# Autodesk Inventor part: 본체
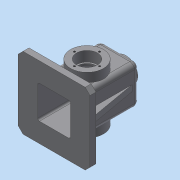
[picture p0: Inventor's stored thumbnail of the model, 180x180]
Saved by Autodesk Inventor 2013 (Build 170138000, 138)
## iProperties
Created: 2018-10
Part Number: 본체
Material: 일반
Document SubType Name: Modeling
Designer: Administrator
Density: 1 g/cm^3
Author: Administrator
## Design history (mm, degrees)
sketch "스케치1"
  geometry: L1 (-32.5, -32.5)-(32.5, -32.5); L2 (32.5, -32.5)-(32.5, 32.5); L3 (32.5, 32.5)-(-32.5, 32.5); L4 (-32.5, 32.5)-(-32.5, -32.5); L5 (-32.5, -32.5)-(32.5, 32.5); L6 (32.5, -32.5)-(-32.5, 32.5); 1 further point
  constraints: 12 end point, 2 midpoint, 2 parallel, 1 horizontal, 1 perpendicular
  dimensions: "d0" = 65 distance of L3.end L2.end; "d1" = 65 distance of L2.end L1.end
extrude "돌출1" new body sketch "스케치1" stored distance "d2" = 110; taper "d3" = 0 deg
fillet "모깎기1" dims "d4" = 8
feature "쉘1" dims "d5" = 5
node "작업 평면1"
sketch "스케치3"
  geometry: C1 r 27.5 at (24.5, 55); 1 further point
  constraints: 1 centre point, 1 coincident
  dimensions: "d10" = 55 diameter of C1
extrude "돌출3" join sketch "스케치3" stored distance "d11" = 15; taper "d12" = 0 deg
sketch "스케치4"
  geometry: C1 r 27.5 at (0, 0) reference; C2 r 17.5 at (0, 0)
  constraints: 1 centre point, 1 coincident
  dimensions: "d13" = 35 diameter of C2
extrude "돌출4" cut sketch "스케치4" distance "d14" = 17; taper "d15" = 0 deg
sketch "스케치5"
  geometry: C1 r 17.5 at (0, 0) reference; C2 r 15 at (0, 0)
  constraints: 1 centre point, 1 coincident
  dimensions: "d16" = 30 diameter of C2
extrude "돌출5" cut sketch "스케치5" distance "d17" = 3; taper "d18" = 0 deg
sketch "스케치6"
  geometry: C1 r 17.5 at (0, 0) reference; 1 further point
  constraints: 1 vertical alignment
  dimensions: "d19" = 21 distance of C1.centre point (0, 21)
hole "구멍1" sketch "스케치6" at (0, 21) diameter "d20" = 3.242; stored, may be unused: countersink angle "d24" = 90 deg, drill point angle "d26" = 118 deg; dims "d21" = 8, "d22" = 4, "d23" = 2, "d25" = 10
node "작업 평면2"
sketch "스케치7"
  geometry: C1 r 20 at (0, 0); 1 further point
  constraints: 1 centre point, 1 coincident
  dimensions: "d31" = 40 diameter of C1
extrude "돌출6" join sketch "스케치7" stored distance "d32" = 3; taper "d33" = 7 deg
hole "구멍2" diameter "d36" = 22.835; stored, may be unused: countersink angle "d40" = 90 deg, drill point angle "d42" = 0 deg; dims "d34" = 10, "d35" = 10, "d37" = 8, "d38" = 4, "d39" = 2, "d41" = 10
sketch "스케치8"
  geometry: L1 (-24.5, -32.5)-(24.5, -32.5) reference; L2 (32.5, -24.5)-(32.5, 24.5) reference; L3 (24.5, 32.5)-(-24.5, 32.5) reference; L4 (-32.5, 24.5)-(-32.5, -24.5) reference; L5 (-60, -60)-(60, -60); L6 (60, -60)-(60, 60); L7 (60, 60)-(-60, 60); L8 (-60, 60)-(-60, -60); L9 (-60, -60)-(60, 60); L10 (60, -60)-(-60, 60); A1 r 8 centre (24.5, -24.5) between (24.5, -32.5) and (32.5, -24.5) reference; A2 r 8 centre (24.5, 24.5) between (32.5, 24.5) and (24.5, 32.5) reference; A3 r 8 centre (-24.5, 24.5) between (-24.5, 32.5) and (-32.5, 24.5) reference; A4 r 8 centre (-24.5, -24.5) between (-32.5, -24.5) and (-24.5, -32.5) reference; 1 further point
  constraints: 12 end point, 2 midpoint, 2 parallel, 1 horizontal, 1 perpendicular
  dimensions: "d43" = 120 distance of L7.end L6.end; "d44" = 120 distance of L6.end L5.end
extrude "돌출7" join sketch "스케치8" distance "d45" = 10; taper "d46" = 0 deg
chamfer "모따기1" distance "d47" = 8; stored, may be unused: second distance "d48" = 2, angle "d49" = 45 deg
sketch "스케치9"
  geometry: L1 (20, 65)-(21.228, 55) reference; L2 (21.228, 55)-(24.5, 55) reference; L3 (32.5, 47)-(32.5, -45) reference; L4 (32.5, -45)-(60, -45) reference; L5 (60, -45)-(60, -55) reference; L6 (60, -55)-(27.5, -55) reference; L7 (27.5, -55)-(27.5, 47) reference; L8 (24.5, 50)-(11.418, 50) reference; L9 (11.418, 50)-(11.418, 65) reference; L10 (11.418, 65)-(20, 65) reference; L11 (-24.5, 55)-(-21.228, 55) reference; L12 (-21.228, 55)-(-20, 65) reference; L13 (-20, 65)-(-11.418, 65) reference; L14 (-11.418, 65)-(-11.418, 50) reference; L15 (-11.418, 50)-(-24.5, 50) reference; L16 (-27.5, 47)-(-27.5, -55) reference; L17 (-27.5, -55)-(-60, -55) reference; L18 (-60, -55)-(-60, -45) reference; L19 (-60, -45)-(-32.5, -45) reference; L20 (-32.5, -45)-(-32.5, 47) reference; L21 (-48, -45)-(-42.191, -12.053); A1 r 8 centre (24.5, 47) between (32.5, 47) and (24.5, 55) reference; A2 r 3 centre (24.5, 47) between (27.5, 47) and (24.5, 50) reference; A3 r 8 centre (-24.5, 47) between (-24.5, 55) and (-32.5, 47) reference; A4 r 3 centre (-24.5, 47) between (-24.5, 50) and (-27.5, 47) reference; 1 further point
  constraints: 2 end point, 1 point on line
  dimensions: "d50" = 10 deg angle of L21 L18; "d51" = 12 distance from line of L21.start L18
feature "리브1" sketch "스케치9" dims "d52" = 1, "d53" = 10, "d54" = 0, "d55" = 0, "d56" = 1, "d57" = 1
sketch "스케치10"
  geometry: L1 (-17.5, -30.5)-(-17.5, -47.5) reference; L2 (-17.5, -47.5)-(-19.379, -47.5) reference; L3 (-19.379, -47.5)-(-19.379, -37.5) reference; L4 (-19.379, -37.5)-(-21, -36.526) reference; L5 (-21, -36.526)-(-22.621, -37.5) reference; L6 (-22.621, -37.5)-(-22.621, -47.5) reference; L7 (-22.621, -47.5)-(-27.5, -47.5) reference; L8 (-27.5, -47.5)-(-27.5, -32.5) reference; L9 (-27.5, -32.5)-(-45, -32.5) reference; L10 (-45, -32.5)-(-45, -60) reference; L11 (-45, -60)-(-55, -60) reference; L12 (-55, -60)-(-55, -27.5) reference; L13 (-55, -27.5)-(-15, -27.5) reference; L14 (-15, -27.5)-(-15, -30.5) reference; L15 (-15, -30.5)-(-17.5, -30.5) reference; L16 (27.5, -32.5)-(27.5, -47.5) reference; L17 (27.5, -47.5)-(22.621, -47.5) reference; L18 (22.621, -47.5)-(22.621, -37.5) reference; L19 (22.621, -37.5)-(21, -36.526) reference; L20 (21, -36.526)-(19.379, -37.5) reference; L21 (19.379, -37.5)-(19.379, -47.5) reference; L22 (19.379, -47.5)-(17.5, -47.5) reference; L23 (17.5, -47.5)-(17.5, -30.5) reference; L24 (17.5, -30.5)-(15, -30.5) reference; L25 (15, -30.5)-(15, -27.5) reference; L26 (15, -27.5)-(47, -27.5) reference; L27 (50, -24.5)-(50, -11.418) reference; L28 (50, -11.418)-(65, -11.418) reference; L29 (65, -11.418)-(65, -20) reference; L30 (65, -20)-(55, -21.228) reference; L31 (55, -21.228)-(55, -24.5) reference; L32 (47, -32.5)-(27.5, -32.5) reference; L33 (27.5, 47.5)-(27.5, 32.5) reference; L34 (27.5, 32.5)-(47, 32.5) reference; L35 (55, 24.5)-(55, 21.228) reference; L36 (55, 21.228)-(65, 20) reference; L37 (65, 20)-(65, 11.418) reference; L38 (65, 11.418)-(50, 11.418) reference; L39 (50, 11.418)-(50, 24.5) reference; L40 (47, 27.5)-(15, 27.5) reference; L41 (15, 27.5)-(15, 30.5) reference; L42 (15, 30.5)-(17.5, 30.5) reference; L43 (17.5, 30.5)-(17.5, 47.5) reference; L44 (17.5, 47.5)-(19.379, 47.5) reference; L45 (19.379, 47.5)-(19.379, 37.5) reference; L46 (19.379, 37.5)-(21, 36.526) reference; L47 (21, 36.526)-(22.621, 37.5) reference; L48 (22.621, 37.5)-(22.621, 47.5) reference; L49 (22.621, 47.5)-(27.5, 47.5) reference; L50 (-27.5, 32.5)-(-27.5, 47.5) reference; L51 (-27.5, 47.5)-(-22.621, 47.5) reference; L52 (-22.621, 47.5)-(-22.621, 37.5) reference; L53 (-22.621, 37.5)-(-21, 36.526) reference; L54 (-21, 36.526)-(-19.379, 37.5) reference; L55 (-19.379, 37.5)-(-19.379, 47.5) reference; L56 (-19.379, 47.5)-(-17.5, 47.5) reference; L57 (-17.5, 47.5)-(-17.5, 30.5) reference; L58 (-17.5, 30.5)-(-15, 30.5) reference; L59 (-15, 30.5)-(-15, 27.5) reference; L60 (-15, 27.5)-(-55, 27.5) reference; L61 (-55, 27.5)-(-55, 60) reference; L62 (-55, 60)-(-45, 60) reference; L63 (-45, 60)-(-45, 32.5) reference; L64 (-45, 32.5)-(-27.5, 32.5) reference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; A1 r 3 centre (47, -24.5) between (47, -27.5) and (50, -24.5) reference; A2 r 8 centre (47, -24.5) between (47, -32.5) and (55, -24.5) reference; A3 r 8 centre (47, 24.5) between (55, 24.5) and (47, 32.5) reference; A4 r 3 centre (47, 24.5) between (50, 24.5) and (47, 27.5) reference; 1 further point
  constraints: 2 end point, 1 parallel, 1 point on line
  dimensions: "d58" = 15 distance between parallel lines of L65 L60
feature "리브2" sketch "스케치10" dims "d59" = 1, "d60" = 6, "d61" = 0, "d62" = 0, "d63" = 1, "d64" = 1
node "솔리드1"
mirror "대칭1"
pattern_circular "원형 패턴1" dims angle "d28" = 360 deg
mirror "대칭2"
mirror "대칭3"
mirror "대칭4"
node "절단 모서리 투영1"
node "절단 모서리 투영2"
other parameters: "d9" = 15
